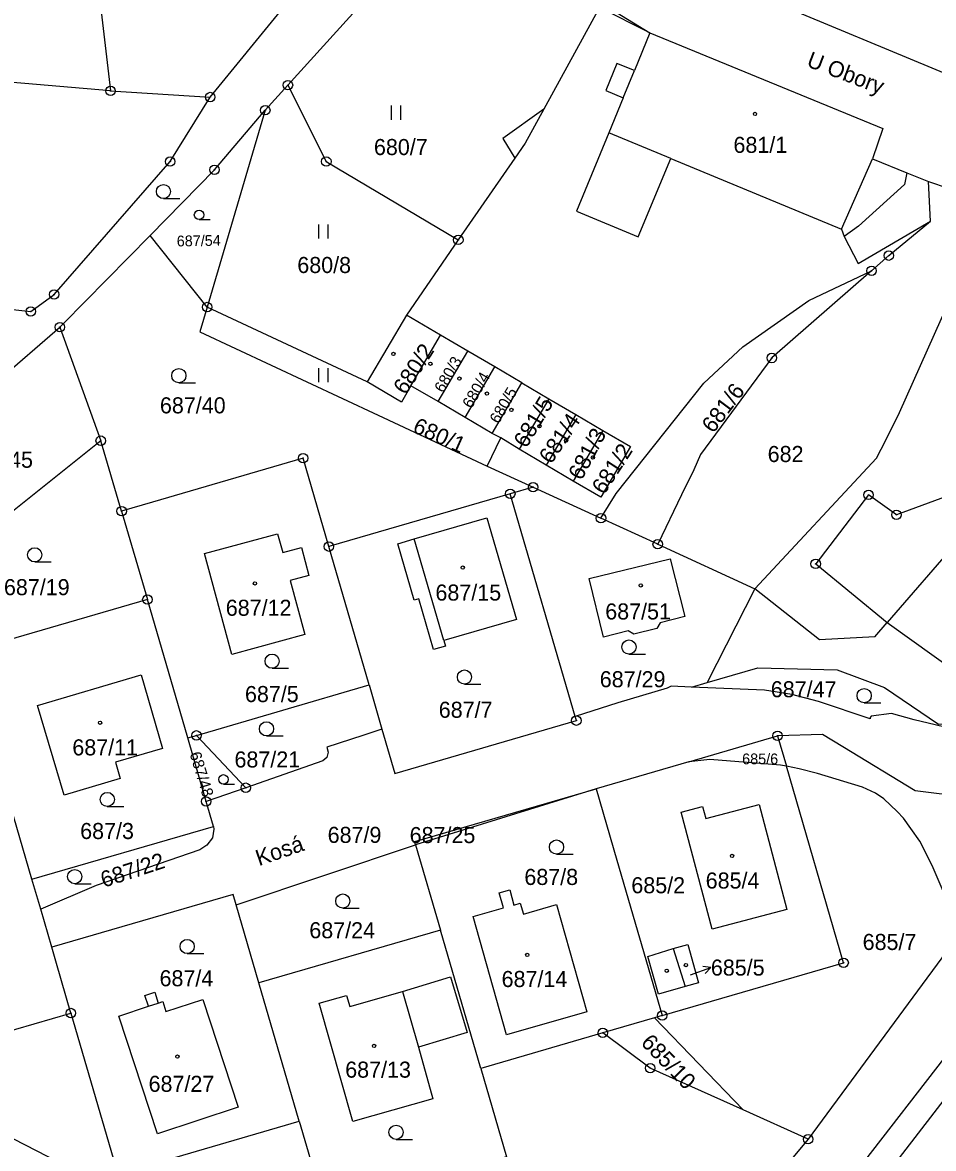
# Model space of a CAD drawing. Extents: x -749778 to -749372, y -967291 to -966955.
# Drawn here: x -749652.7 to -749556.3, y -967221.1 to -967101.9 of the extents above; entities that cross this region are included whole.
import ezdxf

# ---------------------------------------------------------------- set-up
doc = ezdxf.new("R2010")
doc.units = 0
for name, color, linetype in [('Hranice parcel', 7, 'Continuous'), ('Parcelní čísla', 7, 'Continuous'), ('Pop  PČ popisy', 7, 'Continuous'), ('Vnitřní kresba', 7, 'Continuous'), ('Značky bodu BP', 7, 'Continuous'), ('Značky budov', 7, 'Continuous'), ('Značky kultur', 7, 'Continuous')]:
    doc.layers.add(name, color=color, linetype=linetype)

msp = doc.modelspace()

# ---------------------------------------------------------------- linework, layer by layer
at = {"layer": 'Hranice parcel'}
for p, q in [((-749576.24, -967098.5), (-749554.23, -967107.67)), ((-749586.36, -967103.02), (-749591.67, -967100.33)), ((-749643.43, -967109.15), (-749666.45, -967107.14)), ((-749627.05, -967111.2), (-749624.65, -967108.54)), ((-749643.43, -967109.15), (-749632.88, -967109.8)), ((-749627.05, -967111.2), (-749633.19, -967132.02)), ((-749633.19, -967132.02), (-749639.25, -967124.44)), ((-749606.62, -967124.91), (-749612.12, -967132.87)), ((-749616.27, -967139.94), (-749633.19, -967132.02)), ((-749612.12, -967132.87), (-749616.27, -967139.94)), ((-749608.49, -967135), (-749612.12, -967132.87)), ((-749665.32, -967148.46), (-749648.79, -967134.15)), ((-749648.79, -967134.15), (-749644.47, -967146.16)), ((-749611.63, -967140.35), (-749608.49, -967135)), ((-749605.63, -967136.68), (-749608.49, -967135)), ((-749608.77, -967142.03), (-749605.63, -967136.68)), ((-749602.77, -967138.36), (-749605.63, -967136.68)), ((-749605.91, -967143.71), (-749602.77, -967138.36)), ((-749599.91, -967140.04), (-749602.77, -967138.36)), ((-749608.77, -967142.03), (-749611.63, -967140.35)), ((-749603.05, -967145.39), (-749599.91, -967140.04)), ((-749599.91, -967140.04), (-749597.04, -967141.72)), ((-749605.91, -967143.71), (-749608.77, -967142.03)), ((-749597.04, -967141.72), (-749600.18, -967147.07)), ((-749597.04, -967141.72), (-749594.18, -967143.4)), ((-749603.05, -967145.39), (-749605.91, -967143.71)), ((-749594.18, -967143.4), (-749597.32, -967148.75)), ((-749594.18, -967143.4), (-749591.31, -967145.08)), ((-749602.11, -967145.85), (-749603.05, -967145.39)), ((-749591.31, -967145.08), (-749594.45, -967150.43)), ((-749644.47, -967146.16), (-749661.16, -967159.51)), ((-749642.25, -967153.61), (-749644.47, -967146.16)), ((-749603.56, -967148.86), (-749602.11, -967145.85)), ((-749600.18, -967147.07), (-749602.11, -967145.85)), ((-749597.32, -967148.75), (-749600.18, -967147.07)), ((-749603.56, -967148.86), (-749598.71, -967151.08)), ((-749594.45, -967150.43), (-749597.32, -967148.75)), ((-749598.71, -967151.08), (-749601.12, -967151.78)), ((-749598.71, -967151.08), (-749591.52, -967154.37)), ((-749601.12, -967151.78), (-749620.32, -967157.37)), ((-749594.26, -967175.33), (-749601.12, -967151.78)), ((-749642.25, -967153.61), (-749639.53, -967162.97)), ((-749585.52, -967157.12), (-749591.52, -967154.37)), ((-749616.06, -967172.01), (-749620.32, -967157.37)), ((-749585.52, -967157.12), (-749575.24, -967161.82)), ((-749575.24, -967161.82), (-749580.28, -967171.75)), ((-749639.53, -967162.97), (-749658.73, -967168.56)), ((-749635.26, -967177.61), (-749639.53, -967162.97)), ((-749581.95, -967172.24), (-749580.28, -967171.75)), ((-749634.34, -967177.34), (-749616.06, -967172.01)), ((-749616.06, -967172.01), (-749614.7, -967176.68)), ((-749635.26, -967177.61), (-749634.34, -967177.34)), ((-749633.31, -967184.33), (-749635.26, -967177.61)), ((-749634.34, -967177.34), (-749629.11, -967182.88)), ((-749582.24, -967180.13), (-749572.83, -967177.39)), ((-749572.83, -967177.39), (-749571.89, -967180.6)), ((-749582.24, -967180.13), (-749592.03, -967182.99)), ((-749651.74, -967192.56), (-749654.61, -967182.72)), ((-749629.11, -967182.88), (-749633.31, -967184.33)), ((-749592.03, -967182.99), (-749611.14, -967188.93)), ((-749632.54, -967186.97), (-749633.31, -967184.33)), ((-749651.74, -967192.56), (-749632.54, -967186.97)), ((-749630.12, -967195.27), (-749611.14, -967188.93)), ((-749611.14, -967188.93), (-749608.51, -967197.94)), ((-749650.82, -967195.73), (-749651.74, -967192.56)), ((-749649.64, -967199.76), (-749650.82, -967195.73)), ((-749627.72, -967203.53), (-749630.12, -967195.27)), ((-749608.51, -967197.94), (-749627.72, -967203.53)), ((-749604.25, -967212.58), (-749608.51, -967197.94)), ((-749553.95, -967198.86), (-749569.6, -967220.07)), ((-749623.45, -967218.17), (-749627.72, -967203.53)), ((-749666.82, -967212.31), (-749647.62, -967206.72)), ((-749585.87, -967207.23), (-749591.33, -967208.82)), ((-749585.04, -967206.99), (-749585.87, -967207.23)), ((-749585.87, -967207.23), (-749576.49, -967216.97)), ((-749591.33, -967208.82), (-749604.25, -967212.58)), ((-749569.6, -967220.07), (-749576.49, -967216.97))]:
    msp.add_line(p, q, dxfattribs=at)
for points in [[(-749648.62, -967064.74), (-749648.3, -967067.53), (-749647.94, -967070.71), (-749643.43, -967109.15)], [(-749632.88, -967109.8), (-749617.06, -967090.42), (-749615.32, -967085.21)], [(-749615.32, -967085.21), (-749606.8, -967090.45), (-749586.36, -967103.02)], [(-749624.65, -967108.54), (-749609.2, -967091.46), (-749591.67, -967100.33)], [(-749591.67, -967100.33), (-749597.57, -967111.08), (-749601.91, -967114.2), (-749600.64, -967116.26), (-749606.62, -967124.91)], [(-749586.36, -967103.02), (-749561.68, -967113.13), (-749562.79, -967116.35), (-749559.15, -967117.81), (-749556.87, -967118.72)], [(-749624.65, -967108.54), (-749620.59, -967116.62), (-749606.62, -967124.91)], [(-749676.68, -967129.73), (-749651.87, -967132.49), (-749649.4, -967130.69), (-749637.12, -967116.63), (-749632.88, -967109.8)], [(-749639.25, -967124.44), (-749632.43, -967117.5), (-749627.05, -967111.2)], [(-749562.89, -967128.18), (-749561.06, -967126.58), (-749556.64, -967122.92), (-749556.87, -967118.72)], [(-749556.87, -967118.72), (-749552.69, -967120.13), (-749549.11, -967121.42)], [(-749648.79, -967134.15), (-749648.4, -967133.75), (-749639.25, -967124.44)], [(-749591.52, -967154.37), (-749589.9, -967151.74), (-749580.64, -967140.09), (-749576.51, -967136.23), (-749569.51, -967131.32), (-749562.89, -967128.18)], [(-749562.89, -967128.18), (-749573.44, -967137.41), (-749580.98, -967147.62), (-749581.71, -967149.24), (-749582.99, -967151.9), (-749585.52, -967157.12)], [(-749575.24, -967161.82), (-749562.35, -967148.01), (-749561.39, -967146.09), (-749559.94, -967143.18), (-749554, -967129.9)], [(-749554, -967129.9), (-749548.6, -967132), (-749545.4, -967138.1), (-749553.6, -967150.87), (-749554.2, -967151.8), (-749560.25, -967154), (-749563.2, -967151.9), (-749568.8, -967159.2), (-749561.22, -967165.4), (-749549.18, -967174.04), (-749542.77, -967166.07), (-749545.93, -967163), (-749545.74, -967162.82)], [(-749633.19, -967132.02), (-749633.97, -967134.65), (-749615.09, -967143.47), (-749603.56, -967148.86)], [(-749611.63, -967140.35), (-749612.64, -967142.07), (-749616.27, -967139.94)], [(-749591.31, -967145.08), (-749588.4, -967146.79), (-749591.54, -967152.14), (-749594.45, -967150.43)], [(-749620.32, -967157.37), (-749623.05, -967148.01), (-749638.99, -967152.66), (-749642.25, -967153.61)], [(-749603.61, -967154.33), (-749600.48, -967165.08), (-749608.16, -967167.31), (-749607.99, -967167.89), (-749609.24, -967168.25), (-749610.8, -967162.88), (-749611.28, -967163.02), (-749613.01, -967157.07), (-749611.29, -967156.56), (-749603.61, -967154.33)], [(-749633.47, -967158.1), (-749625.75, -967156.01), (-749625.21, -967157.99), (-749623.23, -967157.46), (-749622.44, -967160.41), (-749624.42, -967160.94), (-749622.87, -967166.68), (-749630.59, -967168.77), (-749633.47, -967158.1)], [(-749582.65, -967164.76), (-749585.26, -967165.42), (-749585.62, -967166.02), (-749588.05, -967166.64), (-749588.66, -967166.28), (-749591.26, -967166.94), (-749592.77, -967160.76), (-749584.2, -967158.65), (-749582.65, -967164.76)], [(-749580.28, -967171.75), (-749574.93, -967170.19), (-749566.54, -967170.41), (-749561.52, -967172.29), (-749555.8, -967176.14), (-749551.55, -967175.94), (-749534.4, -967172.34)], [(-749648.35, -967183.67), (-749651.14, -967174.17), (-749640.2, -967170.95), (-749637.92, -967178.72), (-749642.91, -967180.19), (-749642.4, -967181.92), (-749648.35, -967183.67)], [(-749581.95, -967172.24), (-749584.09, -967172.15), (-749584.51, -967172.35), (-749589.74, -967173.9), (-749594.26, -967175.33)], [(-749537.02, -967175.91), (-749538.03, -967174.36), (-749538.28, -967173.97), (-749538.76, -967173.43), (-749541.48, -967175.55), (-749543.56, -967176.77), (-749545.65, -967177.56), (-749547.19, -967177.95), (-749547.26, -967177.59), (-749549.92, -967177.81), (-749550.89, -967177.68), (-749553.79, -967176.8), (-749558.39, -967175.68), (-749560.79, -967175.03), (-749562.93, -967175.31), (-749563.04, -967175.46), (-749563.04, -967175.6), (-749568.49, -967173.77), (-749571.33, -967173.01), (-749574.23, -967172.55), (-749581.95, -967172.24)], [(-749614.7, -967176.68), (-749613.33, -967181.38), (-749594.13, -967175.78), (-749594.26, -967175.33)], [(-749614.7, -967176.68), (-749616.71, -967177.34), (-749620.52, -967178.6), (-749620.41, -967179.11), (-749620.53, -967179.68), (-749620.96, -967180.05), (-749629.11, -967182.88)], [(-749540.92, -967181.19), (-749552.88, -967183.89), (-749558.28, -967183.21), (-749565.92, -967178.54), (-749568.07, -967177.26), (-749572.83, -967177.39)], [(-749571.89, -967180.6), (-749572.51, -967180.48), (-749579.99, -967179.88), (-749582.24, -967180.13)], [(-749585.04, -967206.99), (-749565.84, -967201.4), (-749571.89, -967180.6)], [(-749553.95, -967198.86), (-749554.04, -967198.48), (-749554.32, -967197.29), (-749554.75, -967195.73), (-749555.32, -967193.83), (-749556.46, -967191.11), (-749557.79, -967188.52), (-749558.73, -967187.21), (-749559.52, -967186.11), (-749560.17, -967185.38), (-749561.59, -967184.04), (-749562.48, -967183.46), (-749563.86, -967182.82), (-749568.6, -967181.36), (-749570.54, -967180.87), (-749571.89, -967180.6)], [(-749611.14, -967188.93), (-749611.24, -967188.58), (-749592.03, -967182.99)], [(-749592.03, -967182.99), (-749589.83, -967190.55), (-749585.04, -967206.99)], [(-749580.43, -967186.14), (-749574.77, -967184.65), (-749571.84, -967195.77), (-749579.77, -967197.86), (-749583.03, -967185.48), (-749580.76, -967184.88), (-749580.43, -967186.14)], [(-749632.54, -967186.97), (-749632.49, -967187.26), (-749632.64, -967188.19), (-749633.23, -967188.96), (-749633.98, -967189.45), (-749644.94, -967193.24), (-749650.82, -967195.73)], [(-749630.12, -967195.27), (-749630.44, -967194.17), (-749649.64, -967199.76)], [(-749596.23, -967195.22), (-749593.02, -967206.61), (-749601.53, -967209.01), (-749605.06, -967196.51), (-749601.83, -967195.6), (-749602.28, -967194.01), (-749601.18, -967193.7), (-749600.73, -967195.29), (-749600.06, -967195.1), (-749599.73, -967196.25), (-749596.23, -967195.22)], [(-749576.96, -967239.3), (-749574.4, -967236.29), (-749544.44, -967197.63)], [(-749647.62, -967206.72), (-749649.14, -967201.48), (-749649.64, -967199.76)], [(-749582.34, -967199.46), (-749581.19, -967203.52), (-749582.61, -967203.92), (-749585.43, -967204.73), (-749586.56, -967200.74), (-749583.87, -967199.89), (-749582.34, -967199.46)], [(-749617.77, -967218.2), (-749621.33, -967205.69), (-749618.44, -967204.87), (-749618.11, -967206.02), (-749612.53, -967204.43), (-749607.44, -967202.9), (-749605.67, -967208.79), (-749610.85, -967210.34), (-749609.3, -967215.79), (-749617.77, -967218.2)], [(-749637.91, -967205.5), (-749637.56, -967206.57), (-749633.66, -967205.29), (-749629.92, -967216.68), (-749638.47, -967219.49), (-749642.55, -967207.04), (-749639.42, -967206.01), (-749639.79, -967204.87), (-749638.74, -967204.53), (-749638.37, -967205.67), (-749637.91, -967205.5)], [(-749647.62, -967206.72), (-749642.66, -967223.76), (-749623.45, -967218.17)], [(-749576.49, -967216.97), (-749586.31, -967212.55), (-749591.33, -967208.82)], [(-749604.25, -967212.58), (-749601.52, -967221.94), (-749609.19, -967224.17), (-749616.05, -967236.54)], [(-749662.69, -967215.35), (-749653.68, -967220.04), (-749641.76, -967226.16), (-749629.68, -967230.35), (-749627.23, -967231.85), (-749624.5, -967234)], [(-749623.45, -967218.17), (-749620.73, -967227.53), (-749618.3, -967235.87)], [(-749569.6, -967220.07), (-749572.84, -967223.93), (-749575.56, -967227.17), (-749591.58, -967246.27)]]:
    msp.add_lwpolyline(points, dxfattribs=at)
at = {"layer": 'Pop  PČ popisy'}
for p, q in [((-749582.06, -967202.69), (-749579.89, -967201.9)), ((-749579.89, -967201.9), (-749580.74, -967201.8)), ((-749579.89, -967201.9), (-749580.48, -967202.53))]:
    msp.add_line(p, q, dxfattribs=at)
at = {"layer": 'Vnitřní kresba'}
for p, q in [((-749586.36, -967103.02), (-749587.99, -967107)), ((-749589.84, -967106.24), (-749591.02, -967109.11)), ((-749587.99, -967107), (-749589.84, -967106.24)), ((-749589.16, -967109.87), (-749587.99, -967107)), ((-749591.02, -967109.11), (-749589.16, -967109.87)), ((-749589.16, -967109.87), (-749590.68, -967113.57)), ((-749597.57, -967111.08), (-749599.55, -967114.67)), ((-749590.68, -967113.57), (-749594.13, -967121.88)), ((-749584.12, -967116.29), (-749590.68, -967113.57)), ((-749599.55, -967114.67), (-749600.64, -967116.26)), ((-749587.57, -967124.6), (-749584.12, -967116.29)), ((-749584.12, -967116.29), (-749566.06, -967123.79)), ((-749566.06, -967123.79), (-749562.79, -967116.35)), ((-749559.15, -967117.81), (-749559.39, -967119.06)), ((-749559.39, -967119.06), (-749564.28, -967123.48)), ((-749594.13, -967121.88), (-749587.57, -967124.6)), ((-749564.3, -967127.41), (-749556.64, -967122.92)), ((-749566.06, -967123.79), (-749565.77, -967124.57)), ((-749564.28, -967123.48), (-749565.77, -967124.57)), ((-749565.77, -967124.57), (-749564.3, -967127.41)), ((-749550.63, -967153.13), (-749561.22, -967165.4)), ((-749608.16, -967167.31), (-749611.29, -967156.56)), ((-749568.41, -967167.22), (-749575.24, -967161.82)), ((-749562.54, -967166.93), (-749561.22, -967165.4)), ((-749562.54, -967166.93), (-749568.41, -967167.22)), ((-749583.87, -967199.89), (-749582.61, -967203.92)), ((-749612.53, -967204.43), (-749610.85, -967210.34)), ((-749639.42, -967206.01), (-749638.37, -967205.67)), ((-749554.64, -967215.12), (-749572.33, -967238.1))]:
    msp.add_line(p, q, dxfattribs=at)
at = {"layer": 'Značky bodu BP'}
for centre, radius in [((-749643.43, -967109.15), 0.5), ((-749624.65, -967108.54), 0.5), ((-749624.65, -967108.54), 0.0303), ((-749643.43, -967109.15), 0.0303), ((-749632.88, -967109.8), 0.5), ((-749632.88, -967109.8), 0.0303), ((-749627.05, -967111.2), 0.5), ((-749627.05, -967111.2), 0.0303), ((-749637.12, -967116.63), 0.5), ((-749637.12, -967116.63), 0.0303), ((-749632.43, -967117.5), 0.5), ((-749620.59, -967116.62), 0.5), ((-749620.59, -967116.62), 0.0303), ((-749632.43, -967117.5), 0.0303), ((-749606.62, -967124.91), 0.5), ((-749606.62, -967124.91), 0.0303), ((-749561.06, -967126.58), 0.5), ((-749561.06, -967126.58), 0.0303), ((-749562.89, -967128.18), 0.5), ((-749562.89, -967128.18), 0.0303), ((-749649.4, -967130.69), 0.5), ((-749649.4, -967130.69), 0.0303), ((-749651.87, -967132.49), 0.5), ((-749651.87, -967132.49), 0.0303), ((-749633.19, -967132.02), 0.5), ((-749633.19, -967132.02), 0.0303), ((-749648.79, -967134.15), 0.5), ((-749648.79, -967134.15), 0.0303), ((-749573.44, -967137.41), 0.5), ((-749573.44, -967137.41), 0.0303), ((-749644.47, -967146.16), 0.5), ((-749644.47, -967146.16), 0.0303), ((-749623.05, -967148.01), 0.5), ((-749623.05, -967148.01), 0.0303), ((-749601.12, -967151.78), 0.5), ((-749598.71, -967151.08), 0.5), ((-749598.71, -967151.08), 0.0303), ((-749563.2, -967151.9), 0.5), ((-749601.12, -967151.78), 0.0303), ((-749563.2, -967151.9), 0.0303), ((-749642.25, -967153.61), 0.5), ((-749642.25, -967153.61), 0.0303), ((-749591.52, -967154.37), 0.5), ((-749560.25, -967154), 0.5), ((-749560.25, -967154), 0.0303), ((-749591.52, -967154.37), 0.0303), ((-749620.32, -967157.37), 0.5), ((-749620.32, -967157.37), 0.0303), ((-749585.52, -967157.12), 0.5), ((-749585.52, -967157.12), 0.0303), ((-749568.8, -967159.2), 0.5), ((-749568.8, -967159.2), 0.0303), ((-749639.53, -967162.97), 0.5), ((-749639.53, -967162.97), 0.0303), ((-749594.13, -967175.78), 0.5), ((-749594.13, -967175.78), 0.0303), ((-749634.34, -967177.34), 0.5), ((-749634.34, -967177.34), 0.0303), ((-749572.83, -967177.39), 0.5), ((-749572.83, -967177.39), 0.0303), ((-749629.11, -967182.88), 0.5), ((-749633.31, -967184.33), 0.5), ((-749629.11, -967182.88), 0.0303), ((-749633.31, -967184.33), 0.0303), ((-749565.84, -967201.4), 0.5), ((-749565.84, -967201.4), 0.0303), ((-749647.62, -967206.72), 0.5), ((-749585.04, -967206.99), 0.5), ((-749647.62, -967206.72), 0.0303), ((-749585.04, -967206.99), 0.0303), ((-749591.33, -967208.82), 0.5), ((-749591.33, -967208.82), 0.0303), ((-749586.31, -967212.55), 0.5), ((-749586.31, -967212.55), 0.0303), ((-749569.6, -967220.07), 0.5), ((-749569.6, -967220.07), 0.0303)]:
    msp.add_circle(centre, radius, dxfattribs=at)
at = {"layer": 'Značky budov'}
for centre in [(-749575.22, -967111.58), (-749613.49, -967136.98), (-749609.57, -967138.02), (-749606.5, -967139.59), (-749603.6, -967141.17), (-749601, -967142.9), (-749598.04, -967144.64), (-749595.21, -967146.15), (-749592.38, -967147.94), (-749606.15, -967159.59), (-749628.15, -967161.26), (-749587.31, -967161.48), (-749644.54, -967176), (-749577.64, -967190.09), (-749599.32, -967200.57), (-749582.54, -967201.65), (-749584.56, -967202.24), (-749615.53, -967210.2), (-749636.35, -967211.33)]:
    msp.add_circle(centre, 0.175, dxfattribs=at)
at = {"layer": 'Značky kultur'}
for p, q in [((-749613.69, -967112.2), (-749613.69, -967110.7)), ((-749612.69, -967112.2), (-749612.69, -967110.7)), ((-749637.83, -967120.55), (-749636.08, -967120.55)), ((-749634.06, -967122.77), (-749632.88, -967122.77)), ((-749621.4, -967124.77), (-749621.4, -967123.27)), ((-749620.4, -967124.77), (-749620.4, -967123.27)), ((-749621.38, -967139.97), (-749621.38, -967138.47)), ((-749620.38, -967139.97), (-749620.38, -967138.47)), ((-749636.2, -967140.03), (-749634.45, -967140.03)), ((-749651.45, -967158.99), (-749649.7, -967158.99)), ((-749588.56, -967168.75), (-749586.81, -967168.75)), ((-749626.33, -967170.24), (-749624.58, -967170.24)), ((-749605.97, -967171.92), (-749604.22, -967171.92)), ((-749563.67, -967173.89), (-749561.92, -967173.89)), ((-749626.92, -967177.4), (-749625.17, -967177.4)), ((-749631.47, -967182.5), (-749630.3, -967182.5)), ((-749643.77, -967184.87), (-749642.02, -967184.87)), ((-749596.23, -967189.91), (-749594.48, -967189.91)), ((-749647.22, -967193.04), (-749645.47, -967193.04)), ((-749618.85, -967195.62), (-749617.1, -967195.62)), ((-749635.32, -967200.43), (-749633.57, -967200.43)), ((-749613.21, -967220.09), (-749611.46, -967220.09))]:
    msp.add_line(p, q, dxfattribs=at)
for centre, radius in [((-749637.83, -967119.8), 0.75), ((-749634.06, -967122.27), 0.502), ((-749636.2, -967139.28), 0.75), ((-749651.45, -967158.24), 0.75), ((-749588.56, -967168), 0.75), ((-749626.33, -967169.49), 0.75), ((-749605.97, -967171.17), 0.75), ((-749563.67, -967173.14), 0.75), ((-749626.92, -967176.65), 0.75), ((-749631.48, -967182), 0.502), ((-749643.77, -967184.12), 0.75), ((-749596.23, -967189.16), 0.75), ((-749647.22, -967192.29), 0.75), ((-749618.85, -967194.87), 0.75), ((-749635.32, -967199.68), 0.75), ((-749613.21, -967219.34), 0.75)]:
    msp.add_circle(centre, radius, dxfattribs=at)

# ---------------------------------------------------------------- texts
at = {"layer": 'Parcelní čísla'}
for s, height, p in [('680/7', 1.7, (-749615.55, -967115.94)), ('681/1', 1.7, (-749577.5, -967115.71)), ('680/8', 1.7, (-749623.66, -967128.42)), ('687/40', 1.7, (-749638.2, -967143.27)), ('682', 1.7, (-749573.88, -967148.42)), ('687/45', 1.7, (-749658.59, -967149.03)), ('687/19', 1.7, (-749654.71, -967162.51)), ('687/15', 1.7, (-749609.04, -967163.08)), ('687/12', 1.7, (-749631.23, -967164.69)), ('687/51', 1.7, (-749591.07, -967165.08)), ('687/29', 1.7, (-749591.65, -967172.25)), ('687/47', 1.7, (-749573.55, -967173.31)), ('687/5', 1.7, (-749629.2, -967173.82)), ('687/7', 1.7, (-749608.69, -967175.48)), ('687/11', 1.7, (-749647.47, -967179.46)), ('687/21', 1.7, (-749630.31, -967180.74)), ('685/6', 1.139, (-749576.58, -967180.4)), ('687/3', 1.7, (-749646.64, -967188.31)), ('687/9', 1.7, (-749620.45, -967188.72)), ('687/25', 1.7, (-749611.77, -967188.74)), ('687/8', 1.7, (-749599.63, -967193.17)), ('685/4', 1.7, (-749580.44, -967193.55)), ('685/2', 1.7, (-749588.31, -967194.05)), ('687/24', 1.7, (-749622.39, -967198.81)), ('685/7', 1.7, (-749563.83, -967200.05)), ('685/5', 1.7, (-749579.89, -967202.76)), ('687/4', 1.7, (-749638.24, -967203.89)), ('687/14', 1.7, (-749602.04, -967203.97)), ('687/13', 1.7, (-749618.59, -967213.56)), ('687/27', 1.7, (-749639.4, -967215.06))]:
    msp.add_text(s, height=height, dxfattribs=at).set_placement(p)
for s, height, rotation, p in [('687/54', 1.139, 1, (-749636.41, -967125.61)), ('680/2', 1.7, 57, (-749612.2, -967141.39)), ('680/3', 1.2, 60, (-749608.2, -967141.18)), ('680/4', 1.2, 60, (-749605.23, -967142.83)), ('680/5', 1.2, 60, (-749602.35, -967144.45)), ('681/6', 1.7, 53, (-749579.64, -967145.46)), ('681/5', 1.7, 59, (-749599.42, -967147.04)), ('681/4', 1.7, 56, (-749596.8, -967148.73)), ('680/1', 1.7, 336, (-749611.56, -967145.21)), ('681/3', 1.7, 62, (-749593.58, -967150.45)), ('681/2', 1.7, 57, (-749591.19, -967151.96)), ('687/48', 1.2, 287, (-749635.07, -967179.28)), ('687/22', 1.7, 18, (-749644.15, -967193.47)), ('685/10', 1.7, 314, (-749587.39, -967209.95))]:
    msp.add_text(s, height=height, rotation=rotation, dxfattribs=at).set_placement(p)
at = {"layer": 'Pop  PČ popisy'}
for s, rotation, p in [('U Obory', 339, (-749569.86, -967106.52)), ('Kosá', 19, (-749627.72, -967191.18))]:
    msp.add_text(s, height=1.7, rotation=rotation, dxfattribs=at).set_placement(p)

doc.saveas('drawing.dxf')
